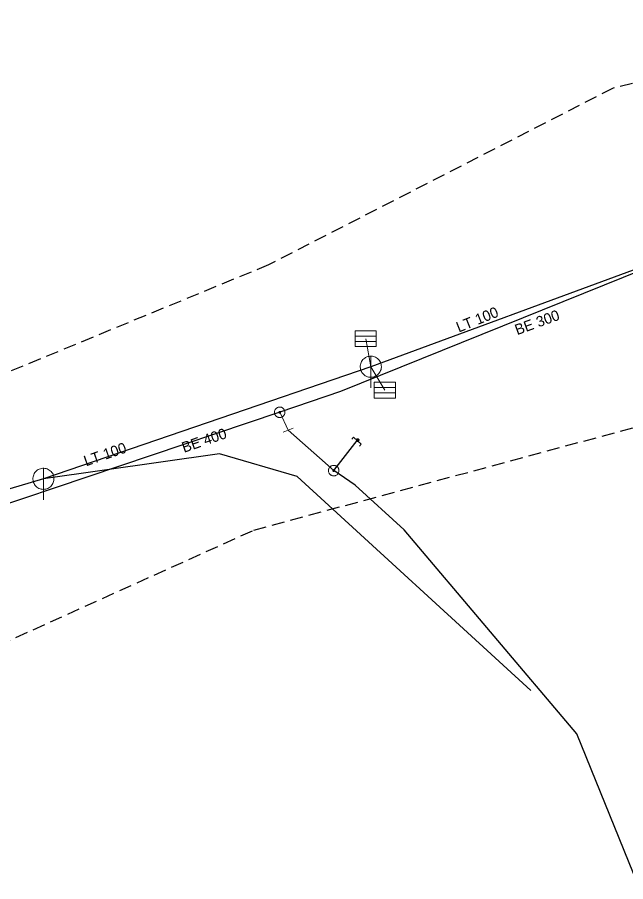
# Model space of a CAD drawing. Extents: x -687387 to -687009, y -972789 to -972578.
# Drawn here: x -687313.5 to -687255.8, y -972748.3 to -972666.4 of the extents above; entities that cross this region are included whole.
import ezdxf

# ---------------------------------------------------------------- set-up
doc = ezdxf.new("R2010")
doc.units = 0
doc.header["$LTSCALE"] = 0.4
doc.linetypes.add('MEDIUM_DASHED', pattern=[4.5, 3, -1.5])
doc.layers.add('1', color=7, linetype='Continuous')
for name, color, linetype, lineweight in [('11', 7, 'Continuous', 13), ('14', 7, 'Continuous', 25), ('17', 7, 'Continuous', 25), ('22', 7, 'Continuous', 13), ('34', 7, 'Continuous', 13), ('47', 7, 'Continuous', 13), ('63', 7, 'MEDIUM_DASHED', 25), ('9', 7, 'Continuous', 13)]:
    doc.layers.add(name, color=color, linetype=linetype, lineweight=lineweight)

msp = doc.modelspace()

# ---------------------------------------------------------------- linework, layer by layer
at = {"layer": '11'}
for p in [(-687280.441, -972696.848), (-687278.627, -972701.719)]:
    msp.add_line(p, (-687279.968, -972699.493), dxfattribs=at)
at = {"layer": '14'}
for p, q in [((-687247.963, -972687.731), (-687279.968, -972699.493)), ((-687279.968, -972699.493), (-687311, -972710.109)), ((-687311, -972710.109), (-687322.482, -972713.486))]:
    msp.add_line(p, q, dxfattribs=at)
at = {"layer": '14', "lineweight": 13}
for p, q in [((-687288.604, -972703.811), (-687287.799, -972705.5)), ((-687281.245, -972706.494), (-687281.209, -972706.438))]:
    msp.add_line(p, q, dxfattribs=at)
at = {"layer": '14'}
msp.add_lwpolyline([(-687264.798, -972730.149), (-687286.945, -972709.903), (-687294.319, -972707.731), (-687311, -972710.109)], dxfattribs=at)
at = {"layer": '17'}
for points in [[(-687239.739, -972685.945), (-687240.857, -972686.329), (-687254.098, -972690.259), (-687282.85, -972701.854), (-687288.604, -972703.811)], [(-687288.604, -972703.811), (-687319.02, -972714.015), (-687347.571, -972726.403)], [(-687287.799, -972705.5), (-687283.483, -972709.333), (-687281.245, -972706.494)], [(-687233.122, -972789.445), (-687233.831, -972788.864), (-687238.279, -972783.932), (-687244.316, -972773.96), (-687260.423, -972734.254), (-687276.818, -972714.934), (-687281.462, -972710.697), (-687283.483, -972709.333)]]:
    msp.add_lwpolyline(points, dxfattribs=at)
at = {"layer": '22'}
for p, q in [((-687281.452, -972696.591), (-687279.452, -972696.591)), ((-687281.452, -972697.091), (-687279.452, -972697.091)), ((-687279.968, -972701.493), (-687279.967, -972698.493)), ((-687279.638, -972701.462), (-687277.638, -972701.462)), ((-687279.638, -972701.962), (-687277.638, -972701.962)), ((-687311, -972712.109), (-687310.999, -972709.109))]:
    msp.add_line(p, q, dxfattribs=at)
for points in [[(-687281.452, -972696.091), (-687279.452, -972696.091), (-687279.452, -972697.591), (-687281.452, -972697.591)], [(-687278.968, -972699.493), (-687278.973, -972699.384), (-687278.991, -972699.276), (-687279.021, -972699.17), (-687279.061, -972699.069), (-687279.113, -972698.972), (-687279.175, -972698.882), (-687279.247, -972698.799), (-687279.327, -972698.725), (-687279.415, -972698.659), (-687279.509, -972698.604), (-687279.609, -972698.559), (-687279.714, -972698.526), (-687279.821, -972698.504), (-687279.93, -972698.494), (-687280.04, -972698.496), (-687280.148, -972698.51), (-687280.255, -972698.535), (-687280.358, -972698.572), (-687280.456, -972698.621), (-687280.548, -972698.679), (-687280.634, -972698.748), (-687280.711, -972698.825), (-687280.78, -972698.911), (-687280.839, -972699.003), (-687280.887, -972699.101), (-687280.924, -972699.204), (-687280.95, -972699.311), (-687280.964, -972699.419), (-687280.967, -972699.529), (-687280.957, -972699.638), (-687280.936, -972699.745), (-687280.902, -972699.849), (-687280.858, -972699.949), (-687280.803, -972700.044), (-687280.737, -972700.132), (-687280.663, -972700.212), (-687280.58, -972700.284), (-687280.49, -972700.346), (-687280.394, -972700.398), (-687280.292, -972700.439), (-687280.187, -972700.469), (-687280.079, -972700.487), (-687279.969, -972700.493), (-687279.86, -972700.487), (-687279.752, -972700.469), (-687279.647, -972700.44), (-687279.545, -972700.399), (-687279.448, -972700.347), (-687279.358, -972700.285), (-687279.275, -972700.214), (-687279.2, -972700.134), (-687279.135, -972700.046), (-687279.079, -972699.952), (-687279.035, -972699.852), (-687279.001, -972699.748), (-687278.979, -972699.64), (-687278.969, -972699.531)], [(-687279.638, -972700.962), (-687277.638, -972700.962), (-687277.638, -972702.462), (-687279.638, -972702.462)], [(-687310, -972710.109), (-687310.005, -972710), (-687310.023, -972709.892), (-687310.053, -972709.786), (-687310.093, -972709.685), (-687310.145, -972709.588), (-687310.207, -972709.498), (-687310.279, -972709.415), (-687310.359, -972709.341), (-687310.447, -972709.275), (-687310.541, -972709.22), (-687310.641, -972709.175), (-687310.746, -972709.142), (-687310.853, -972709.12), (-687310.962, -972709.11), (-687311.072, -972709.112), (-687311.18, -972709.126), (-687311.287, -972709.151), (-687311.39, -972709.188), (-687311.488, -972709.237), (-687311.58, -972709.295), (-687311.666, -972709.364), (-687311.743, -972709.441), (-687311.812, -972709.527), (-687311.871, -972709.619), (-687311.919, -972709.717), (-687311.956, -972709.82), (-687311.982, -972709.927), (-687311.996, -972710.035), (-687311.999, -972710.145), (-687311.989, -972710.254), (-687311.968, -972710.361), (-687311.934, -972710.465), (-687311.89, -972710.565), (-687311.835, -972710.66), (-687311.769, -972710.748), (-687311.695, -972710.828), (-687311.612, -972710.9), (-687311.522, -972710.962), (-687311.426, -972711.014), (-687311.324, -972711.055), (-687311.219, -972711.085), (-687311.111, -972711.103), (-687311.001, -972711.109), (-687310.892, -972711.103), (-687310.784, -972711.085), (-687310.679, -972711.056), (-687310.577, -972711.015), (-687310.48, -972710.963), (-687310.39, -972710.901), (-687310.307, -972710.83), (-687310.232, -972710.75), (-687310.167, -972710.662), (-687310.111, -972710.568), (-687310.067, -972710.468), (-687310.033, -972710.364), (-687310.011, -972710.256), (-687310.001, -972710.147)]]:
    msp.add_lwpolyline(points, close=True, dxfattribs=at)
at = {"layer": '34'}
msp.add_line((-687287.333, -972705.317), (-687288.264, -972705.681), dxfattribs=at)
at = {"layer": '47'}
for points in [[(-687288.127, -972703.659), (-687288.146, -972703.61), (-687288.169, -972703.563), (-687288.197, -972703.52), (-687288.229, -972703.479), (-687288.267, -972703.441), (-687288.308, -972703.408), (-687288.351, -972703.38), (-687288.398, -972703.356), (-687288.446, -972703.336), (-687288.496, -972703.322), (-687288.549, -972703.313), (-687288.601, -972703.311), (-687288.653, -972703.313), (-687288.705, -972703.321), (-687288.755, -972703.334), (-687288.804, -972703.353), (-687288.851, -972703.376), (-687288.895, -972703.405), (-687288.935, -972703.436), (-687288.973, -972703.474), (-687289.006, -972703.515), (-687289.035, -972703.558), (-687289.059, -972703.605), (-687289.079, -972703.653), (-687289.092, -972703.703), (-687289.101, -972703.756), (-687289.104, -972703.808), (-687289.101, -972703.86), (-687289.093, -972703.912), (-687289.08, -972703.962), (-687289.061, -972704.011), (-687289.038, -972704.058), (-687289.01, -972704.102), (-687288.978, -972704.142), (-687288.94, -972704.18), (-687288.9, -972704.213), (-687288.857, -972704.242), (-687288.81, -972704.267), (-687288.761, -972704.286), (-687288.711, -972704.299), (-687288.658, -972704.308), (-687288.607, -972704.311), (-687288.554, -972704.308), (-687288.502, -972704.3), (-687288.452, -972704.287), (-687288.403, -972704.268), (-687288.356, -972704.245), (-687288.313, -972704.217), (-687288.272, -972704.185), (-687288.234, -972704.147), (-687288.201, -972704.107), (-687288.172, -972704.064), (-687288.148, -972704.017), (-687288.129, -972703.968), (-687288.115, -972703.918), (-687288.106, -972703.865), (-687288.104, -972703.814), (-687288.106, -972703.761), (-687288.114, -972703.709)], [(-687288.525, -972703.786), (-687288.528, -972703.777), (-687288.532, -972703.77), (-687288.537, -972703.763), (-687288.542, -972703.756), (-687288.548, -972703.75), (-687288.555, -972703.745), (-687288.562, -972703.74), (-687288.57, -972703.736), (-687288.578, -972703.733), (-687288.586, -972703.73), (-687288.595, -972703.729), (-687288.603, -972703.729), (-687288.612, -972703.729), (-687288.62, -972703.73), (-687288.628, -972703.732), (-687288.637, -972703.735), (-687288.644, -972703.739), (-687288.651, -972703.744), (-687288.658, -972703.749), (-687288.664, -972703.755), (-687288.669, -972703.762), (-687288.674, -972703.769), (-687288.678, -972703.777), (-687288.682, -972703.785), (-687288.684, -972703.793), (-687288.685, -972703.802), (-687288.685, -972703.81), (-687288.685, -972703.819), (-687288.684, -972703.827), (-687288.682, -972703.835), (-687288.679, -972703.844), (-687288.675, -972703.851), (-687288.67, -972703.858), (-687288.665, -972703.865), (-687288.659, -972703.871), (-687288.653, -972703.877), (-687288.645, -972703.881), (-687288.637, -972703.885), (-687288.629, -972703.889), (-687288.621, -972703.891), (-687288.612, -972703.892), (-687288.604, -972703.892), (-687288.595, -972703.892), (-687288.587, -972703.891), (-687288.579, -972703.889), (-687288.57, -972703.886), (-687288.563, -972703.882), (-687288.556, -972703.877), (-687288.549, -972703.872), (-687288.543, -972703.866), (-687288.537, -972703.86), (-687288.533, -972703.852), (-687288.529, -972703.844), (-687288.526, -972703.836), (-687288.523, -972703.828), (-687288.522, -972703.819), (-687288.522, -972703.811), (-687288.522, -972703.802), (-687288.523, -972703.794)], [(-687283.016, -972709.152), (-687283.038, -972709.104), (-687283.064, -972709.059), (-687283.095, -972709.017), (-687283.13, -972708.978), (-687283.169, -972708.943), (-687283.212, -972708.912), (-687283.258, -972708.887), (-687283.305, -972708.866), (-687283.355, -972708.849), (-687283.406, -972708.838), (-687283.459, -972708.833), (-687283.511, -972708.834), (-687283.563, -972708.839), (-687283.614, -972708.85), (-687283.663, -972708.866), (-687283.711, -972708.888), (-687283.756, -972708.914), (-687283.799, -972708.946), (-687283.837, -972708.98), (-687283.872, -972709.019), (-687283.903, -972709.062), (-687283.929, -972709.108), (-687283.95, -972709.156), (-687283.966, -972709.205), (-687283.977, -972709.256), (-687283.982, -972709.309), (-687283.982, -972709.361), (-687283.976, -972709.413), (-687283.965, -972709.464), (-687283.949, -972709.513), (-687283.927, -972709.561), (-687283.901, -972709.606), (-687283.87, -972709.649), (-687283.835, -972709.687), (-687283.796, -972709.722), (-687283.754, -972709.753), (-687283.708, -972709.779), (-687283.66, -972709.801), (-687283.61, -972709.816), (-687283.559, -972709.827), (-687283.506, -972709.832), (-687283.455, -972709.832), (-687283.402, -972709.826), (-687283.351, -972709.815), (-687283.302, -972709.799), (-687283.254, -972709.777), (-687283.209, -972709.751), (-687283.167, -972709.72), (-687283.128, -972709.685), (-687283.093, -972709.646), (-687283.062, -972709.604), (-687283.036, -972709.558), (-687283.015, -972709.51), (-687282.999, -972709.46), (-687282.988, -972709.409), (-687282.983, -972709.356), (-687282.984, -972709.305), (-687282.989, -972709.252), (-687283, -972709.201)], [(-687283.406, -972709.303), (-687283.409, -972709.294), (-687283.414, -972709.288), (-687283.419, -972709.281), (-687283.425, -972709.275), (-687283.431, -972709.269), (-687283.438, -972709.264), (-687283.446, -972709.259), (-687283.453, -972709.256), (-687283.462, -972709.254), (-687283.47, -972709.251), (-687283.479, -972709.251), (-687283.487, -972709.251), (-687283.496, -972709.252), (-687283.504, -972709.253), (-687283.512, -972709.256), (-687283.521, -972709.259), (-687283.527, -972709.264), (-687283.534, -972709.269), (-687283.54, -972709.275), (-687283.546, -972709.281), (-687283.551, -972709.288), (-687283.556, -972709.296), (-687283.559, -972709.303), (-687283.562, -972709.312), (-687283.564, -972709.32), (-687283.564, -972709.329), (-687283.564, -972709.337), (-687283.563, -972709.346), (-687283.562, -972709.354), (-687283.559, -972709.362), (-687283.556, -972709.371), (-687283.551, -972709.377), (-687283.546, -972709.384), (-687283.54, -972709.39), (-687283.534, -972709.396), (-687283.528, -972709.401), (-687283.519, -972709.406), (-687283.512, -972709.409), (-687283.503, -972709.412), (-687283.495, -972709.414), (-687283.486, -972709.414), (-687283.478, -972709.414), (-687283.469, -972709.413), (-687283.461, -972709.412), (-687283.453, -972709.409), (-687283.444, -972709.406), (-687283.438, -972709.401), (-687283.431, -972709.396), (-687283.425, -972709.39), (-687283.419, -972709.384), (-687283.414, -972709.378), (-687283.409, -972709.369), (-687283.406, -972709.362), (-687283.404, -972709.353), (-687283.401, -972709.345), (-687283.401, -972709.336), (-687283.401, -972709.328), (-687283.402, -972709.319), (-687283.403, -972709.311)]]:
    msp.add_lwpolyline(points, close=True, dxfattribs=at)
msp.add_lwpolyline([(-687281.78, -972706.344), (-687281.61, -972706.158), (-687280.879, -972706.829), (-687281.049, -972707.014)], dxfattribs=at)
at = {"layer": '63'}
msp.add_lwpolyline([(-687147.303, -972666.399), (-687234.11, -972667.795), (-687234.11, -972667.795), (-687256.998, -972673.098), (-687256.998, -972673.098), (-687289.655, -972689.845), (-687289.655, -972689.845), (-687341.85, -972711.338), (-687341.85, -972711.338), (-687347.712, -972701.568), (-687347.712, -972701.568), (-687372.554, -972712.454), (-687357.202, -972748.182), (-687357.202, -972748.182), (-687324.545, -972735.9), (-687324.545, -972735.9), (-687325.103, -972730.318), (-687325.103, -972730.318), (-687291.05, -972714.966), (-687291.05, -972714.966), (-687198.94, -972690.124), (-687198.94, -972690.124), (-687142.558, -972685.938)], dxfattribs=at)
at = {"layer": '9'}
for points in [[(-687281.335, -972706.438), (-687281.335, -972706.451), (-687281.333, -972706.464), (-687281.33, -972706.477), (-687281.325, -972706.489), (-687281.319, -972706.501), (-687281.312, -972706.512), (-687281.304, -972706.522), (-687281.294, -972706.532), (-687281.284, -972706.54), (-687281.273, -972706.547), (-687281.261, -972706.553), (-687281.249, -972706.558), (-687281.236, -972706.561), (-687281.223, -972706.563), (-687281.21, -972706.565), (-687281.197, -972706.564), (-687281.184, -972706.562), (-687281.171, -972706.559), (-687281.159, -972706.554), (-687281.147, -972706.548), (-687281.136, -972706.541), (-687281.126, -972706.533), (-687281.116, -972706.523), (-687281.108, -972706.513), (-687281.101, -972706.502), (-687281.095, -972706.49), (-687281.09, -972706.478), (-687281.087, -972706.465), (-687281.085, -972706.452), (-687281.083, -972706.439), (-687281.084, -972706.426), (-687281.086, -972706.413), (-687281.089, -972706.4), (-687281.094, -972706.388), (-687281.1, -972706.376), (-687281.107, -972706.365), (-687281.115, -972706.355), (-687281.125, -972706.345), (-687281.135, -972706.337), (-687281.146, -972706.33), (-687281.158, -972706.324), (-687281.17, -972706.319), (-687281.183, -972706.316), (-687281.196, -972706.314), (-687281.209, -972706.313), (-687281.222, -972706.313), (-687281.235, -972706.315), (-687281.248, -972706.318), (-687281.26, -972706.323), (-687281.272, -972706.329), (-687281.283, -972706.336), (-687281.293, -972706.344), (-687281.303, -972706.354), (-687281.311, -972706.364), (-687281.318, -972706.375), (-687281.324, -972706.387), (-687281.329, -972706.399), (-687281.332, -972706.412), (-687281.334, -972706.425)], [(-687281.315, -972706.438), (-687281.316, -972706.449), (-687281.314, -972706.46), (-687281.311, -972706.471), (-687281.307, -972706.481), (-687281.302, -972706.491), (-687281.296, -972706.5), (-687281.289, -972706.509), (-687281.281, -972706.517), (-687281.272, -972706.524), (-687281.263, -972706.53), (-687281.253, -972706.535), (-687281.243, -972706.539), (-687281.232, -972706.542), (-687281.221, -972706.545), (-687281.21, -972706.545), (-687281.199, -972706.545), (-687281.188, -972706.543), (-687281.177, -972706.54), (-687281.167, -972706.536), (-687281.157, -972706.531), (-687281.148, -972706.525), (-687281.139, -972706.518), (-687281.131, -972706.51), (-687281.124, -972706.501), (-687281.118, -972706.492), (-687281.113, -972706.482), (-687281.109, -972706.472), (-687281.106, -972706.461), (-687281.104, -972706.45), (-687281.103, -972706.439), (-687281.103, -972706.428), (-687281.105, -972706.417), (-687281.108, -972706.406), (-687281.112, -972706.396), (-687281.117, -972706.386), (-687281.123, -972706.377), (-687281.13, -972706.368), (-687281.138, -972706.36), (-687281.147, -972706.353), (-687281.156, -972706.347), (-687281.166, -972706.342), (-687281.176, -972706.338), (-687281.187, -972706.335), (-687281.198, -972706.333), (-687281.209, -972706.333), (-687281.22, -972706.332), (-687281.231, -972706.334), (-687281.242, -972706.337), (-687281.252, -972706.341), (-687281.262, -972706.346), (-687281.271, -972706.352), (-687281.28, -972706.359), (-687281.288, -972706.367), (-687281.295, -972706.376), (-687281.301, -972706.385), (-687281.306, -972706.395), (-687281.31, -972706.405), (-687281.313, -972706.416), (-687281.315, -972706.427)], [(-687281.296, -972706.438), (-687281.296, -972706.447), (-687281.295, -972706.456), (-687281.292, -972706.465), (-687281.289, -972706.473), (-687281.285, -972706.481), (-687281.28, -972706.489), (-687281.274, -972706.496), (-687281.268, -972706.502), (-687281.261, -972706.508), (-687281.253, -972706.513), (-687281.245, -972706.517), (-687281.237, -972706.52), (-687281.228, -972706.523), (-687281.219, -972706.524), (-687281.21, -972706.526), (-687281.201, -972706.525), (-687281.192, -972706.524), (-687281.183, -972706.521), (-687281.175, -972706.518), (-687281.167, -972706.514), (-687281.159, -972706.509), (-687281.152, -972706.503), (-687281.146, -972706.497), (-687281.14, -972706.49), (-687281.135, -972706.482), (-687281.131, -972706.474), (-687281.128, -972706.466), (-687281.125, -972706.457), (-687281.124, -972706.448), (-687281.122, -972706.439), (-687281.123, -972706.43), (-687281.124, -972706.421), (-687281.127, -972706.412), (-687281.13, -972706.404), (-687281.134, -972706.396), (-687281.139, -972706.388), (-687281.145, -972706.381), (-687281.151, -972706.375), (-687281.158, -972706.369), (-687281.166, -972706.364), (-687281.174, -972706.36), (-687281.182, -972706.357), (-687281.191, -972706.354), (-687281.2, -972706.353), (-687281.209, -972706.352), (-687281.218, -972706.352), (-687281.227, -972706.353), (-687281.236, -972706.356), (-687281.244, -972706.359), (-687281.252, -972706.363), (-687281.26, -972706.368), (-687281.267, -972706.374), (-687281.273, -972706.38), (-687281.279, -972706.387), (-687281.284, -972706.395), (-687281.288, -972706.403), (-687281.291, -972706.411), (-687281.294, -972706.42), (-687281.295, -972706.429)], [(-687281.276, -972706.438), (-687281.276, -972706.445), (-687281.275, -972706.452), (-687281.274, -972706.459), (-687281.271, -972706.465), (-687281.268, -972706.471), (-687281.264, -972706.477), (-687281.26, -972706.483), (-687281.255, -972706.488), (-687281.249, -972706.492), (-687281.243, -972706.496), (-687281.237, -972706.499), (-687281.231, -972706.502), (-687281.224, -972706.503), (-687281.217, -972706.506), (-687281.21, -972706.506), (-687281.203, -972706.506), (-687281.196, -972706.504), (-687281.189, -972706.503), (-687281.183, -972706.5), (-687281.176, -972706.497), (-687281.171, -972706.493), (-687281.165, -972706.489), (-687281.16, -972706.484), (-687281.156, -972706.478), (-687281.152, -972706.472), (-687281.149, -972706.466), (-687281.146, -972706.46), (-687281.144, -972706.453), (-687281.143, -972706.446), (-687281.142, -972706.439), (-687281.142, -972706.432), (-687281.143, -972706.425), (-687281.145, -972706.418), (-687281.148, -972706.412), (-687281.151, -972706.405), (-687281.155, -972706.4), (-687281.159, -972706.394), (-687281.164, -972706.389), (-687281.17, -972706.385), (-687281.175, -972706.381), (-687281.182, -972706.378), (-687281.188, -972706.375), (-687281.195, -972706.373), (-687281.202, -972706.372), (-687281.209, -972706.372), (-687281.216, -972706.372), (-687281.223, -972706.372), (-687281.23, -972706.374), (-687281.236, -972706.377), (-687281.242, -972706.38), (-687281.248, -972706.384), (-687281.254, -972706.388), (-687281.259, -972706.393), (-687281.263, -972706.399), (-687281.267, -972706.404), (-687281.27, -972706.411), (-687281.273, -972706.417), (-687281.274, -972706.424), (-687281.276, -972706.431)], [(-687281.256, -972706.438), (-687281.256, -972706.443), (-687281.256, -972706.448), (-687281.255, -972706.453), (-687281.253, -972706.457), (-687281.251, -972706.462), (-687281.248, -972706.466), (-687281.245, -972706.469), (-687281.241, -972706.473), (-687281.238, -972706.476), (-687281.234, -972706.479), (-687281.229, -972706.481), (-687281.225, -972706.483), (-687281.22, -972706.484), (-687281.215, -972706.486), (-687281.21, -972706.486), (-687281.205, -972706.486), (-687281.2, -972706.485), (-687281.195, -972706.484), (-687281.191, -972706.482), (-687281.186, -972706.48), (-687281.182, -972706.477), (-687281.178, -972706.474), (-687281.175, -972706.47), (-687281.172, -972706.467), (-687281.169, -972706.463), (-687281.167, -972706.458), (-687281.165, -972706.454), (-687281.164, -972706.449), (-687281.163, -972706.444), (-687281.162, -972706.439), (-687281.162, -972706.434), (-687281.163, -972706.429), (-687281.164, -972706.424), (-687281.166, -972706.42), (-687281.168, -972706.415), (-687281.171, -972706.411), (-687281.174, -972706.407), (-687281.177, -972706.404), (-687281.181, -972706.401), (-687281.185, -972706.398), (-687281.19, -972706.396), (-687281.194, -972706.394), (-687281.199, -972706.393), (-687281.204, -972706.392), (-687281.209, -972706.392), (-687281.214, -972706.392), (-687281.219, -972706.393), (-687281.224, -972706.393), (-687281.228, -972706.395), (-687281.233, -972706.397), (-687281.237, -972706.4), (-687281.24, -972706.403), (-687281.244, -972706.406), (-687281.247, -972706.41), (-687281.25, -972706.414), (-687281.252, -972706.419), (-687281.254, -972706.423), (-687281.255, -972706.428), (-687281.256, -972706.433)], [(-687281.236, -972706.438), (-687281.236, -972706.441), (-687281.237, -972706.444), (-687281.236, -972706.446), (-687281.235, -972706.449), (-687281.234, -972706.452), (-687281.232, -972706.454), (-687281.23, -972706.456), (-687281.228, -972706.458), (-687281.226, -972706.46), (-687281.224, -972706.462), (-687281.221, -972706.464), (-687281.218, -972706.465), (-687281.216, -972706.465), (-687281.213, -972706.466), (-687281.21, -972706.466), (-687281.207, -972706.466), (-687281.204, -972706.466), (-687281.201, -972706.465), (-687281.199, -972706.464), (-687281.196, -972706.463), (-687281.194, -972706.461), (-687281.191, -972706.459), (-687281.189, -972706.457), (-687281.188, -972706.455), (-687281.186, -972706.453), (-687281.185, -972706.45), (-687281.183, -972706.447), (-687281.183, -972706.445), (-687281.182, -972706.442), (-687281.181, -972706.439), (-687281.182, -972706.436), (-687281.182, -972706.433), (-687281.183, -972706.43), (-687281.184, -972706.428), (-687281.185, -972706.425), (-687281.187, -972706.423), (-687281.188, -972706.42), (-687281.19, -972706.418), (-687281.193, -972706.417), (-687281.195, -972706.415), (-687281.198, -972706.414), (-687281.2, -972706.413), (-687281.203, -972706.412), (-687281.206, -972706.412), (-687281.209, -972706.411), (-687281.212, -972706.412), (-687281.215, -972706.411), (-687281.217, -972706.413), (-687281.22, -972706.413), (-687281.223, -972706.414), (-687281.225, -972706.416), (-687281.227, -972706.417), (-687281.229, -972706.419), (-687281.231, -972706.422), (-687281.233, -972706.424), (-687281.234, -972706.427), (-687281.235, -972706.429), (-687281.236, -972706.432), (-687281.236, -972706.435)], [(-687281.217, -972706.438), (-687281.217, -972706.44), (-687281.217, -972706.44), (-687281.216, -972706.44), (-687281.216, -972706.442), (-687281.217, -972706.443), (-687281.215, -972706.443), (-687281.215, -972706.443), (-687281.215, -972706.445), (-687281.215, -972706.445), (-687281.214, -972706.446), (-687281.212, -972706.446), (-687281.212, -972706.446), (-687281.212, -972706.447), (-687281.21, -972706.447), (-687281.21, -972706.447), (-687281.209, -972706.447), (-687281.208, -972706.447), (-687281.208, -972706.446), (-687281.207, -972706.446), (-687281.205, -972706.446), (-687281.205, -972706.445), (-687281.205, -972706.445), (-687281.204, -972706.444), (-687281.204, -972706.444), (-687281.202, -972706.443), (-687281.202, -972706.442), (-687281.201, -972706.441), (-687281.201, -972706.441), (-687281.201, -972706.44), (-687281.201, -972706.439), (-687281.201, -972706.438), (-687281.201, -972706.437), (-687281.201, -972706.437), (-687281.202, -972706.436), (-687281.202, -972706.435), (-687281.203, -972706.434), (-687281.203, -972706.434), (-687281.204, -972706.433), (-687281.204, -972706.433), (-687281.205, -972706.432), (-687281.206, -972706.432), (-687281.207, -972706.431), (-687281.207, -972706.431), (-687281.208, -972706.431), (-687281.209, -972706.431), (-687281.21, -972706.431), (-687281.211, -972706.431), (-687281.211, -972706.431), (-687281.212, -972706.432), (-687281.213, -972706.431), (-687281.214, -972706.433), (-687281.214, -972706.433), (-687281.215, -972706.433), (-687281.215, -972706.433), (-687281.216, -972706.435), (-687281.216, -972706.436), (-687281.216, -972706.437), (-687281.217, -972706.437), (-687281.217, -972706.438)]]:
    msp.add_lwpolyline(points, close=True, dxfattribs=at)

# ---------------------------------------------------------------- texts
at = {"layer": '1'}
for s, rotation, p in [('LT 100', 22, (-687271.625, -972696.264)), ('BE 300', 20, (-687266.096, -972696.51)), ('BE 400', 19, (-687297.679, -972707.651)), ('LT 100', 19, (-687306.969, -972708.933))]:
    msp.add_text(s, height=1, rotation=rotation, dxfattribs=at).set_placement(p)

doc.saveas('drawing.dxf')
